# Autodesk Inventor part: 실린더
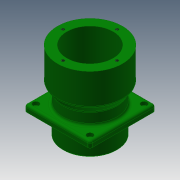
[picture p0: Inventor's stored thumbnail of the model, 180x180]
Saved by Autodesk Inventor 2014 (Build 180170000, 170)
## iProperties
Created: 2016-11
Part Number: 실린더
Material: 알루미늄 6061
Document SubType Name: Modeling
Designer: mduedu
Density: 2.71 g/cm^3
Mass: 551.099 g
Surface Area: 551.337 cm^2
Volume: 203.358 cm^3
Appearance: 진녹색
Author: mduedu
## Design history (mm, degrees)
sketch "스케치1"
  geometry: L1 (0, 0)-(0, 101); L2 (30, 0)-(30, 101); L3 (30, 101)-(42, 101); L4 (42, 101)-(42, 61); L5 (42, 61)-(35, 51); L6 (35, 51)-(35, 0); L7 (35, 0)-(30, 0)
  constraints: 14 end point, 4 parallel, 2 horizontal alignment, 1 perpendicular, 1 vertical
  dimensions: "d0" = 101 distance of L1.start L1.end; "d1" = 60 diameter of L2.end L1; "d2" = 84 diameter of L3.end L1; "d3" = 70 diameter of L6.end L1; "d4" = 40 distance of L3.end L4.end; "d5" = 50 vertical distance of L5.end L3.end
revolve "회전1" sketch "스케치1" stored, may be unused: angle "d6" = 90 deg
node "작업 평면1"
sketch "스케치2"
  geometry: L1 (-42.5, -42.5)-(42.5, -42.5); L2 (42.5, -42.5)-(42.5, 42.5); L3 (42.5, 42.5)-(-42.5, 42.5); L4 (-42.5, 42.5)-(-42.5, -42.5); L5 (-42.5, -42.5)-(42.5, 42.5); L6 (42.5, -42.5)-(-42.5, 42.5); C1 r 35 at (0, 0) reference; C2 r 35 at (0, 0); 1 further point
  constraints: 12 end point, 2 midpoint, 2 parallel, 2 perpendicular, 1 centre point, 1 coincident, 1 concentric, 1 horizontal
  dimensions: "d8" = 85 distance of L2.end L3.end
extrude "돌출1" join sketch "스케치2" distance "d10" = 8; taper "d11" = 0 deg
fillet "모깎기1" dims "d12" = 3
fillet "모깎기2" dims "d13" = 3
chamfer "모따기1" distance "d14" = 1; stored, may be unused: second distance "d15" = 2, angle "d16" = 45 deg
chamfer "모따기2" distance "d17" = 5; stored, may be unused: second distance "d18" = 2, angle "d19" = 15 deg
sketch "스케치3"
  geometry: L1 (-35, -35)-(35, -35); L2 (35, -35)-(35, 35); L3 (35, 35)-(-35, 35); L4 (-35, 35)-(-35, -35); L5 (-35, -35)-(35, 35); L6 (35, -35)-(-35, 35); 5 further points
  constraints: 12 end point, 4 coincident, 2 midpoint, 2 parallel, 1 horizontal, 1 perpendicular
  dimensions: "d20" = 70 distance of L3.end L2.end; "d21" = 70 distance of L2.end L1.end
sketch "스케치4"
  geometry: 4 further points
  constraints: 4 other
hole "구멍1" sketch "스케치4" at (-35, 35), (35, 35), (35, -35), (-35, -35) diameter "d22" = 4.5; stored, may be unused: countersink angle "d26" = 90 deg, drill point angle "d28" = 0 deg; dims "d23" = 6, "d24" = 8, "d25" = 4.6, "d27" = 8
sketch "스케치5"
  geometry: 4 further points
  constraints: 4 other
hole "구멍2" sketch "스케치5" at (0, -35), (35, 0), (-35, 0), (0, 35) diameter "d29" = 4.134; stored, may be unused: countersink angle "d33" = 90 deg, drill point angle "d35" = 120 deg; dims "d30" = 7.5, "d31" = 4, "d32" = 2, "d34" = 10
node "솔리드1"
other parameters: "d7" = -27
